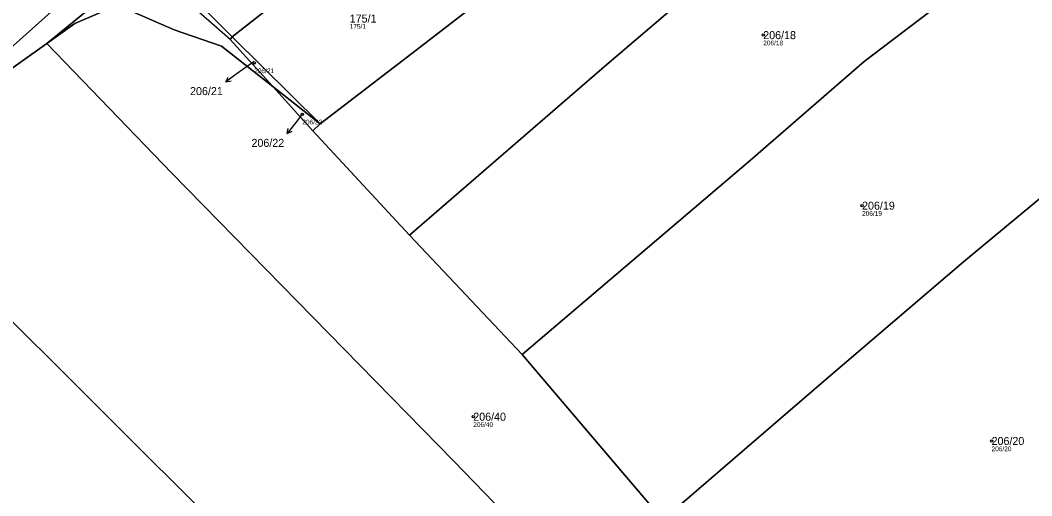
# Model space of a CAD drawing. Extents: x -734504 to -730695, y -1027923 to -1024502.
# Drawn here: x -731983.6 to -731768.7, y -1027510.7 to -1027409.7 of the extents above; entities that cross this region are included whole.
import ezdxf

# ---------------------------------------------------------------- set-up
doc = ezdxf.new("R2010")
doc.units = 0
for name, color, linetype in [('Definiční body', 7, 'Continuous'), ('Hranice parcel', 7, 'Continuous'), ('Parcelní čísla', 7, 'Continuous'), ('Polygon parcely', 7, 'Continuous'), ('Pop  PČ popisy', 7, 'Continuous')]:
    doc.layers.add(name, color=color, linetype=linetype)

msp = doc.modelspace()

# ---------------------------------------------------------------- linework, layer by layer
at = {"layer": 'Definiční body'}
for centre in [(-731825.73, -1027412.89), (-731933.87, -1027418.8), (-731923.66, -1027429.69), (-731804.73, -1027449.11), (-731887.34, -1027493.94), (-731777.21, -1027499.1)]:
    msp.add_circle(centre, 0.25, dxfattribs=at)
at = {"layer": 'Hranice parcel'}
for p, q in [((-731908.21, -1027389.36), (-731938.53, -1027413.23)), ((-731955.51, -1027396.28), (-731938.53, -1027413.23)), ((-731977.96, -1027414.64), (-731957.22, -1027397.68)), ((-731939, -1027413.79), (-731957.22, -1027397.68)), ((-731938.53, -1027413.23), (-731939, -1027413.79)), ((-731939, -1027413.79), (-731929.91, -1027423.82)), ((-731938.53, -1027413.23), (-731919.88, -1027431.72)), ((-732008.36, -1027436.27), (-731977.96, -1027414.64)), ((-731929.91, -1027423.82), (-731919.88, -1027431.72)), ((-731929.91, -1027423.82), (-731921.42, -1027433.18)), ((-731919.88, -1027431.72), (-731921.42, -1027433.18)), ((-731921.42, -1027433.18), (-731900.9, -1027455.36)), ((-731900.9, -1027455.36), (-731876.94, -1027480.69)), ((-731876.94, -1027480.69), (-731847.06, -1027515.85))]:
    msp.add_line(p, q, dxfattribs=at)
for points in [[(-731900.9, -1027455.36), (-731858.96, -1027419.13), (-731842.66, -1027405.18), (-731819.23, -1027386.25), (-731803.82, -1027373.76), (-731769.49, -1027350.46)], [(-731876.94, -1027480.69), (-731828.4, -1027439.46), (-731804.26, -1027418.47), (-731778.43, -1027398.82), (-731765.74, -1027389.61), (-731754.2, -1027380.66)], [(-731959.4, -1027392.4), (-731969.01, -1027400.69), (-731989.76, -1027419.29), (-732007.12, -1027433.26)], [(-731919.88, -1027431.72), (-731900.42, -1027416.82), (-731882.47, -1027402.93), (-731874.93, -1027397.11)], [(-731977.96, -1027414.64), (-731971.99, -1027410.39), (-731962.95, -1027406.54), (-731950.87, -1027411.76), (-731940.83, -1027415.21), (-731929.91, -1027423.82)], [(-731811.62, -1027585.27), (-731844.33, -1027552.09), (-731891.47, -1027503.4), (-731951.38, -1027442.23), (-731977.96, -1027414.64)], [(-731847.06, -1027515.85), (-731812.34, -1027485.99), (-731783.2, -1027461.01), (-731765.35, -1027446.24), (-731739.08, -1027423.45)], [(-731838.8, -1027620.86), (-731876.38, -1027583.2), (-731940.49, -1027518.38), (-731992.95, -1027466.17)]]:
    msp.add_lwpolyline(points, dxfattribs=at)
at = {"layer": 'Polygon parcely'}
for points in [[(-731769.49, -1027350.46), (-731781.26, -1027328.05), (-731785.51, -1027331.1), (-731796.26, -1027339.14), (-731798.71, -1027340.95), (-731821.27, -1027357.61), (-731841.11, -1027372.22), (-731849.51, -1027378.41), (-731854.81, -1027382.25), (-731874.93, -1027397.11), (-731882.47, -1027402.93), (-731900.42, -1027416.82), (-731919.88, -1027431.72), (-731921.42, -1027433.18), (-731900.9, -1027455.36), (-731858.96, -1027419.13), (-731842.66, -1027405.18), (-731819.23, -1027386.25), (-731803.82, -1027373.76)], [(-731769.49, -1027350.46), (-731803.82, -1027373.76), (-731819.23, -1027386.25), (-731842.66, -1027405.18), (-731858.96, -1027419.13), (-731900.9, -1027455.36), (-731876.94, -1027480.69), (-731828.4, -1027439.46), (-731804.26, -1027418.47), (-731778.43, -1027398.82), (-731765.74, -1027389.61), (-731754.2, -1027380.66)], [(-731913.92, -1027375.68), (-731927.13, -1027370.87), (-731955.51, -1027396.28), (-731938.53, -1027413.23), (-731908.21, -1027389.36)], [(-731938.53, -1027413.23), (-731919.88, -1027431.72), (-731900.42, -1027416.82), (-731882.47, -1027402.93), (-731874.93, -1027397.11), (-731887.41, -1027406.07), (-731902.56, -1027385.55), (-731898.05, -1027381.85), (-731898.4, -1027381.37), (-731900.12, -1027382.98), (-731908.21, -1027389.36)], [(-731739.08, -1027423.45), (-731747.7, -1027407.95), (-731754.2, -1027380.66), (-731765.74, -1027389.61), (-731778.43, -1027398.82), (-731804.26, -1027418.47), (-731828.4, -1027439.46), (-731876.94, -1027480.69), (-731847.06, -1027515.85), (-731812.34, -1027485.99), (-731783.2, -1027461.01), (-731765.35, -1027446.24)], [(-731959.4, -1027392.4), (-731969.01, -1027400.69), (-731989.76, -1027419.29), (-732007.12, -1027433.26), (-732008.36, -1027436.27), (-731977.96, -1027414.64), (-731957.22, -1027397.68), (-731955.51, -1027396.28)], [(-731955.51, -1027396.28), (-731957.22, -1027397.68), (-731939, -1027413.79), (-731938.53, -1027413.23)], [(-731950.87, -1027411.76), (-731940.83, -1027415.21), (-731929.91, -1027423.82), (-731939, -1027413.79), (-731957.22, -1027397.68), (-731977.96, -1027414.64), (-731971.99, -1027410.39), (-731962.95, -1027406.54)], [(-731811.62, -1027585.27), (-731804.97, -1027577.61), (-731797.32, -1027569.39), (-731802.85, -1027565.08), (-731847.06, -1027515.85), (-731876.94, -1027480.69), (-731900.9, -1027455.36), (-731921.42, -1027433.18), (-731929.91, -1027423.82), (-731940.83, -1027415.21), (-731950.87, -1027411.76), (-731962.95, -1027406.54), (-731971.99, -1027410.39), (-731977.96, -1027414.64), (-731951.38, -1027442.23), (-731891.47, -1027503.4), (-731844.33, -1027552.09)], [(-731938.53, -1027413.23), (-731939, -1027413.79), (-731929.91, -1027423.82), (-731919.88, -1027431.72)], [(-731811.62, -1027585.27), (-731844.33, -1027552.09), (-731891.47, -1027503.4), (-731951.38, -1027442.23), (-731977.96, -1027414.64), (-732008.36, -1027436.27), (-732015.01, -1027441.72), (-731992.95, -1027466.17), (-731940.49, -1027518.38), (-731876.38, -1027583.2), (-731838.8, -1027620.86), (-731835.1, -1027614.91), (-731820.88, -1027595.95)], [(-731921.42, -1027433.18), (-731919.88, -1027431.72), (-731929.91, -1027423.82)], [(-731802.85, -1027565.08), (-731797.32, -1027569.39), (-731773.49, -1027548.23), (-731762.75, -1027539.46), (-731745.83, -1027524.46), (-731731.88, -1027512.34), (-731726.4, -1027506.3), (-731720.45, -1027497.8), (-731719.67, -1027487.82), (-731719.65, -1027476.16), (-731720.04, -1027469.74), (-731721.74, -1027462.66), (-731727.16, -1027449.17), (-731739.08, -1027423.45), (-731765.35, -1027446.24), (-731783.2, -1027461.01), (-731812.34, -1027485.99), (-731847.06, -1027515.85)], [(-731876.38, -1027583.2), (-731940.49, -1027518.38), (-731992.95, -1027466.17), (-732029.4, -1027487.81), (-732012.45, -1027506.02), (-731977.29, -1027541.45), (-731950.17, -1027568.94), (-731917.96, -1027599.29), (-731883.16, -1027631.87), (-731859.14, -1027651.52), (-731852.83, -1027640.63), (-731844.77, -1027630.45), (-731838.8, -1027620.86)]]:
    msp.add_lwpolyline(points, close=True, dxfattribs=at)
msp.add_lwpolyline([(-731989.76, -1027419.29), (-731969.01, -1027400.69)], dxfattribs=at)
at = {"layer": 'Pop  PČ popisy'}
for p, q in [((-731933.91, -1027418.46), (-731937.47, -1027421.03)), ((-731937.47, -1027421.03), (-731939.9, -1027422.79)), ((-731939.9, -1027422.79), (-731939.38, -1027421.8)), ((-731939.9, -1027422.79), (-731938.79, -1027422.61)), ((-731925.01, -1027431.42), (-731926.86, -1027433.79)), ((-731923.66, -1027429.69), (-731925.01, -1027431.42)), ((-731926.86, -1027433.79), (-731926.64, -1027432.69)), ((-731926.86, -1027433.79), (-731925.85, -1027433.3))]:
    msp.add_line(p, q, dxfattribs=at)

# ---------------------------------------------------------------- texts
at = {"layer": 'Definiční body'}
for s, p in [('175/1', (-731913.59, -1027411.53)), ('206/18', (-731825.73, -1027415.05)), ('206/21', (-731933.87, -1027420.96)), ('206/22', (-731923.66, -1027431.85)), ('206/19', (-731804.73, -1027451.27)), ('206/40', (-731887.34, -1027496.1)), ('206/20', (-731777.21, -1027501.26))]:
    msp.add_text(s, height=1, dxfattribs=at).set_placement(p)
at = {"layer": 'Parcelní čísla'}
for s, p in [('175/1', (-731913.59, -1027410.22)), ('206/18', (-731825.73, -1027413.74)), ('206/21', (-731947.51, -1027425.62)), ('206/22', (-731934.46, -1027436.62)), ('206/19', (-731804.73, -1027449.96)), ('206/40', (-731887.34, -1027494.79)), ('206/20', (-731777.21, -1027499.95))]:
    msp.add_text(s, height=1.7, dxfattribs=at).set_placement(p)

doc.saveas('drawing.dxf')
